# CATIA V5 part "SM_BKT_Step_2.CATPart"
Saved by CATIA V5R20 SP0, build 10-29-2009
Part number: SM_BKT
Bounding box of the stored display mesh (mm): x 0 to 137.579, y 0 to 228.383, z 0 to 43
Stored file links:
  C:\Users\CAS\Desktop\GSD_Class_Parts\SM_BKT_Step_2.CATPart
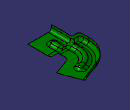
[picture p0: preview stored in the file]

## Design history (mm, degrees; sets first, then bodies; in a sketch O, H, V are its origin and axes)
Set1 "CONST_GEO"
  Point1: type OnCurve, Support Sketch1, Length 10
Set2 "Inputs"
  Sketch1 "Flange Sketch" on xy-plane, origin (0, 0, 0), H (1, 0, 0), V (0, 1, 0)
    point P1 (0, -20)
    line L1 (0, -20) -> (0, 125)
    arc A1 centre (90, 125) radius 90 from (0, 125) to (59.2182, 209.5723) cw
    point P3 (90, 125)
    line L2 (59.2182, 209.5723) -> (120.2982, 231.8036)
    radius A1 = 90
    distance H P3 = 125
    angle L1 L2 = 110
    length L2 = 65
    distance H P1 = 20
    coincidence: P1 V
    vertical: L1 V
    tangency: A1 L1, A1 L2
  Sketch2 "Main Body Sketch" on yz-plane, origin (0, 0, 0), H (0, 1, 0), V (0, 0, 1)
    point P1 (-20, 0)
    line L1 (-20, 0) -> (75, 0)
    point P2 (75, 0)
    line L2 (75, 0) -> (100, 25)
    line L3 (100, 25) -> (275, 25)
    reference intersected line E1 through (0, 0) direction (0, 1) from zx-plane
    distance V P1 = 20
    angle L1 L2 = 45
    distance L1 L3 = 25
    distance E1 P2 = 75
    length L3 = 175
    horizontal: L1 H, L3 H
    coincidence: H L1
Set3 "Spliting Elements"
  Plane1: type Normal, Curve Sketch1, RefPoint Point1
  Offset1: Offset Extrude2, Length 78
  Extract1: ExtractElem edge [face of Fillet3 | face of Extrude2 from Sketch1.L1]
  CurvePar1: Offset Extract1, Support Fillet3, Offset2 0, Offset1 8
Set4 "Final"
  Split1: ToCut Fillet3, Cutting (CurvePar1; Plane1; Offset1; zx-plane)
Set5 "Operations"
  Extrude1: Element1 Sketch2, Lim1 300, Lim2 300
  Fillet1: radius 25, on edge [face of Extrude1 from Sketch2.L2 | face of Extrude1 from Sketch2.L1]
  Fillet2: radius 20, on edge [face of Extrude1 from Sketch2.L3 | face of Extrude1 from Sketch2.L2]
  Extrude2: Element1 Sketch1, Lim1 200, Lim2 200
  Fillet3: type BiTangent, Element1 Fillet2, Element2 Extrude2, Radius 10
  Offset2: Offset Extrude2, Length -35
  Intersect1: ToIntersect1 Offset2, ToIntersect2 Split1
  Point2: type OnCurve, Support Intersect1, Length 35
  Point3: type OnCurve, Support Intersect1, Length 35
  Plane2: type Normal, Curve Intersect1, RefPoint Point2
  Plane3: type Normal, Curve Intersect1, RefPoint Point3
  Sweep1: type Circle, Guide Intersect1, Radius 8
  Intersect2: ToIntersect1 Sweep1, ToIntersect2 Plane2
  Intersect3: ToIntersect1 Sweep1, ToIntersect2 Plane3
  Fill1: Boundary Intersect2
  Fill2: Boundary Intersect3
  Fillet4: type BiTangent, Element1 Sweep1, Radius 6, Element2 Fill1
  Fillet5: type BiTangent, Element1 Fillet4, Radius 6, Element2 Fill2
  Fillet6: type BiTangent, Element1 Split1, Element2 Fillet5, Radius 12
Body1 (main body)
